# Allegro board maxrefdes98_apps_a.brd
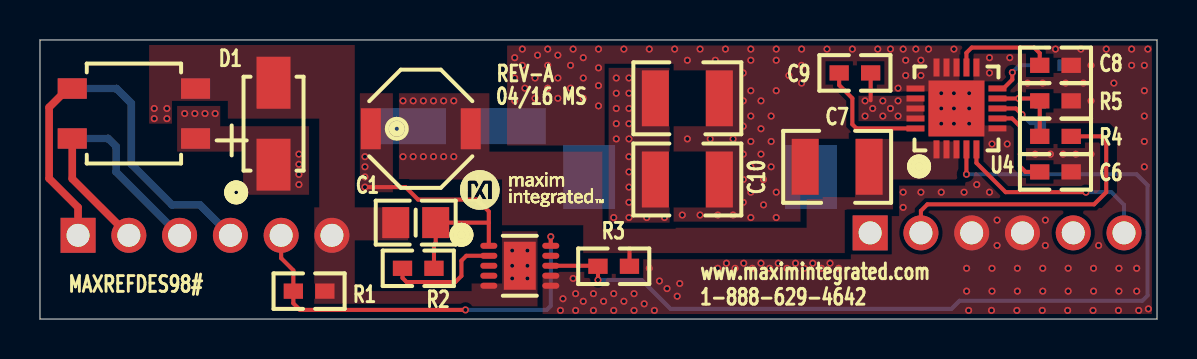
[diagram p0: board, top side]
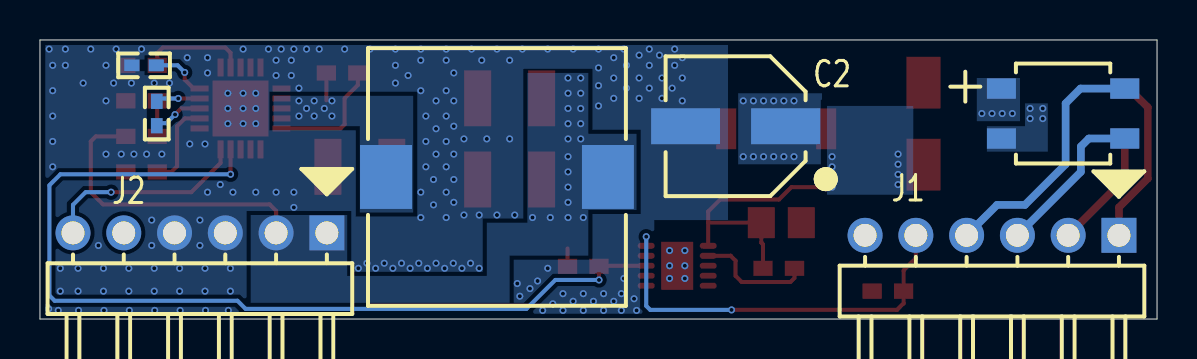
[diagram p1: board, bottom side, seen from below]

Outline 55.88 x 13.97 mm; copper layers: TOP, BOTTOM. Coordinates in mm from the lower left corner of the outline.
Outline path: 0,13.97 55.88,13.97 55.88,0 0,0 0,13.97

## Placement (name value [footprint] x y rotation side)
C1  0.1UF  [0805]  18.8 4.83 0 top
C2  22UF  [CAPAE660X770M]  21.08 9.65 0 bottom
C4  22UF  [1210]  32.39 11.05 180 top
C5  1PF  [0402]  50.04 10.29 270 bottom
C6  0.018UF  [0603]  50.8 7.37 180 top
C7  2.2UF  [1210]  39.88 7.62 0 top
C8  2.2UF  [0603]  50.8 12.7 180 top
C9  0.1UF  [0603]  40.77 12.32 0 top
C10  22UF  [1210]  32.39 6.99 180 top
D1  58V  [DIO_SMA]  11.68 9.78 90 top
EV_KIT_BOX2  MEDIUM BOX  [EVKIT_PACKAGING]  41.91 -5.21 0 top
J1  TSW-106-25-T-S-RA  [SAMTEC_TSW-106-25-X-S-RA]  1.91 4.19 0 bottom
J2  TSW-106-25-T-S-RA  [SAMTEC_TSW-106-25-X-S-RA]  41.53 4.31 0 bottom
L1  3.3UH  [IND_SD53]  19.05 9.53 0 top
L2  15UH  [IND_SLF12575]  33.02 7.11 180 bottom
NOREF  -  []  27.94 64.77 0 top
NOREF#2  -  []  21.99 6.46 0 top
NOREF#3  -  []  55.88 0 90 top
NOREF#4  -  []  0 13.97 0 top
NOREF#5  -  []  137.16 -26.04 0 top
R1  619  [0603]  13.46 1.4 180 top
R2  24.9K  [0603]  18.92 2.54 0 top
R3  3.3M  [0603]  28.7 2.64 0 top
R4  154K  [0603]  50.8 9.14 0 top
R5  34K  [0603]  50.8 10.92 180 top
R6  68K  [0402]  50.67 12.7 180 bottom
U1  KMB110F  [SOTFL125P680X160-4M]  4.7 10.29 180 top
U2  KMB110F  [SOTFL125P680X160-4M]  4.7 10.29 180 bottom
U3  MAX5969AETB+  [SON50P300X300X80-11WEED3M]  24 2.67 0 top
U4  MAX17503ATP+  [QFN50P400X400X80-21W5M]  45.85 10.54 90 top

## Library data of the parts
C1 = CAP_NP: part number: CAP_NP_0805CAP-0805,0.1UF,20-000U1-A41
C2 = CAP_POL: part number: CAP_POL_CASE_D8-CAPAE660X770M,22UF,20-0022U-59D
C4 C10 = CAP_NP: alternate symbols: CAPC3225X270L; part number: CAP_NP_1210CAP-1210,22UF,20-0022U-T7A
C5 = CAP_NP: alternate symbols: (0402_NOSILK); part number: CAP_NP_0402CAP-0402,1PF,20-0001P-32
C6 = CAP_NP: alternate symbols: (0603_NOSILK); part number: CAP_NP_0603CAP-0603,0.018UF,20-0U018-14
C7 = CAP_NP: alternate symbols: CAPC3225X270L; part number: CAP_NP_1210CAP-1210,2.2UF,20-002U2-Q1
C8 = CAP_NP: alternate symbols: 0603_NOSILK,CAPC1608X90L; part number: CAP_NP_0603CAP-0603,2.2UF,20-002U2-10
C9 = CAP_NP: alternate symbols: 0603_NOSILK,CAPC1608X90L; part number: CAP_NP_0603CAP-0603,0.1UF,20-000U1-11C
D1 = DIO_TVS: part number: DIO_TVS_UNI-DIRECT-DIO_SMA,58V,30-SMAJ58A13F-00
EV_KIT_BOX2 = EV_KIT_BOX: part number: EV_KIT_BOX_ACCESSORY-N/A,MEDIUM BOX,EVKIT_PACKAGING
J1 J2 = HEADER_6P: part number: HEADER_6P_RA-SAMTEC_TSW-106-25-X-S-RA,TSW-106-25-T-S-RA,01-TSW10625TSRA6P-19
L1 = INDUCT: part number: INDUCT_IND_SD53-IND_SD53,3.3UH,50-003U3-SM10
L2 = INDUCT: part number: INDUCT_IND_SLF12575-IND_SLF12575,15UH,50-0015U-0IU
R1 = RES: alternate symbols: (0603_NOSILK); part number: RES_0603RES-0603,619,80-0619R-24
R2 = RES: alternate symbols: 0603_NOSILK,RESC1608X90L; part number: RES_0603RES-0603,24.9K,80-024K9-24
R3 = RES: alternate symbols: (0603_NOSILK); part number: RES_0603RES-0603,3.3M,80-003M3-24
R4 = RES: alternate symbols: (0603_NOSILK); part number: RES_0603RES-0603,154K,80-0154K-24
R5 = RES: alternate symbols: (0603_NOSILK); part number: RES_0603RES-0603,34K,80-0034K-24
R6 = RES: alternate symbols: (0402_NOSILK,RESC1005X50L); part number: RES_0402RES-0402,68K,80-0068K-23
U1 U2 = DIO_SCHOTTKY_4P: part number: DIO_SCHOTTKY_4P_SMT-SOTFL125P680X160-4M,KMB110F,30-KMB110F-00
U3 = MAX5969: part number: MAX5969_TDFN10-EP-SON50P300X300X80-11WEED3M,MAX5969AETB+,10-MAX5969AETB-T
U4 = MAX17503: part number: MAX17503_TQFN20-EP-QFN50P400X400X80-21W5M,MAX17503ATP+,10-MAX17503ATP-T

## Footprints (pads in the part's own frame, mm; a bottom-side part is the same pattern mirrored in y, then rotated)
0402
  rect 0.762x0.584 smd: 1(-0.61,0) 2(0.61,0)
0603
  rect 0.965x0.762 smd: 1(-0.787,0) 2(0.787,0)
0805
  rect 1.35x1.55 smd: 1(-1,0) 2(1,0)
1210
  rect 1.35x2.8 smd: 1(-1.6,0) 2(1.6,0)
CAPAE660X770M
  rect 3.45x1.8 smd: 1(-2.5,0) 2(2.5,0)
DIO_SMA
  rect 2.6x1.7 smd: A(2.05,0) C(-2.05,0)
IND_SD53
  rect 1x2.05 smd: 1(-2.5,0) 2(2.5,0)
IND_SLF12575
  rect 2.6x3.2 smd: 1(-5.55,0) 2(5.55,0)
QFN50P400X400X80-21W5M
  rect 0.9x0.3 smd: 1(-2.05,1) 2(-2.05,0.5) 3(-2.05,0) 4(-2.05,-0.5) 5(-2.05,-1) 11(2.05,-1) 12(2.05,-0.5) 13(2.05,0) 14(2.05,0.5) 15(2.05,1)
  rect 0.3x0.9 smd: 6(-1,-2.05) 7(-0.5,-2.05) 8(0,-2.05) 9(0.5,-2.05) 10(1,-2.05) 16(1,2.05) 17(0.5,2.05) 18(0,2.05) 19(-0.5,2.05) 20(-1,2.05)
  rect 2.8x2.8 smd: 21(0,0)
SAMTEC_TSW-106-25-X-S-RA
  rect 1.75x1.75 hole 1.15: 1(0,0)
  round 1.75 hole 1.15: 2(2.54,0) 3(5.08,0) 4(7.62,0) 5(10.16,0) 6(12.7,0)
SON50P300X300X80-11WEED3M
  oval 0.85x0.3 smd: 1(-1.55,1) 2(-1.55,0.5) 3(-1.55,0) 4(-1.55,-0.5) 5(-1.55,-1) 6(1.55,-1) 7(1.55,-0.5) 8(1.55,0) 9(1.55,0.5) 10(1.55,1)
  rect 1.6x2.4 smd: 11(0,0)
SOTFL125P680X160-4M
  rect 1.45x1.02 smd: 1(-3.085,1.25) 2(-3.085,-1.25) 3(3.085,-1.25) 4(3.085,1.25)

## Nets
ADJ: C5.1 R4.1 R5.2 U4.9(FB)
CP1: J1.5 R1.2 U3.10(CLS)
CP2: C1.1 D1.A J1.6 R1.1 U1.2(-) U2.2(-) U3.5(VSS) U3.11(EP)
PG: R3.1 U3.8(PG) U4.4(EN/UVLO)
RST: J2.6 U4.5(RESET)
SUPPLY_0: C2.2(B) C4.1 C6.1 C7.1 C8.1 C10.1 J2.3 J2.4 R5.1 R6.1 U3.6(RTN) U3.7(WAD) U4.6(SYNC) U4.11(MODE) U4.13(SGND) U4.14(PGND1) U4.15(PGND2) U4.16(PGND3) U4.21(EP)
UNNAMED_1_CAPNP_I5_2: C1.2 D1.C(K) L1.1 R2.2 U1.1(+) U2.1(+) U3.1(VDD)
UNNAMED_1_CAPNP_I12_2: C6.2 U4.7(SS)
UNNAMED_1_CAPNP_I16_2: C2.1(A) C7.2 L1.2 R3.2 U4.1(VIN1) U4.2(VIN2) U4.3(VIN3)
UNNAMED_1_CAPNP_I17_2: C8.2 U4.12(VCC)
UNNAMED_1_CAPNP_I19_2: C4.2 C10.2 J2.1 J2.2 L2.2 R4.2
UNNAMED_1_CAPNP_I23_1: C9.1 U4.20(BST)
UNNAMED_1_CAPNP_I23_2: C9.2 L2.1 U4.17(LX1) U4.18(LX2) U4.19(LX3)
UNNAMED_1_CAPNP_I26_2: C5.2 U4.8(CF)
UNNAMED_1_MAX5969_I24_DET: R2.1 U3.2(DET)
UNNAMED_1_MAX17503_I11_RT: R6.2 U4.10(RT)
VA1: J1.1 U1.3(AC1)
VA2: J1.2 U1.4(AC2)
VB1: J1.3 U2.3(AC1)
VB2: J1.4 U2.4(AC2)

Pads without a net: J2 5; U3 3 4 9

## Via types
v1: diameter 0.356, hole 0.203, TOP to BOTTOM, 261 vias

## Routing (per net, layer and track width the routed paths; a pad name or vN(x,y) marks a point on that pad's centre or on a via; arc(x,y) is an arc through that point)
ADJ: length 5.1
  TOP w0.203: R4.1 R5.2 49.89,11.04 v1(48.96,11.04) U4.9
  BOTTOM w0.203: v1(48.96,11.04) 49.89,11.04 C5.1
CP1: length 20.7
  TOP w0.203: v1(21.29,0.46) 13,0.46 12.67,0.79 R1.2 12.67,2.44 12.07,3.05 J1.5 ; U3.10 v1(25.55,4.12)
  BOTTOM w0.203: v1(21.29,0.46) 25.35,0.46 25.55,0.66 v1(25.55,4.12)
CP2: length 0.3
  TOP w0.203: 22.18,1.67 U3.5
  vias: v1(5.71,10.54) v1(5.71,10.03) v1(6.35,10.54) v1(6.35,10.03) v1(23.62,3.43) v1(23.62,2.67) v1(23.62,2.03) v1(24.38,3.43) v1(24.38,2.67) v1(24.38,2.03)
PG: length 47.5
  TOP w0.203: U3.8 27.89,2.67 R3.1 v1(27.91,1.96) ; U4.4 v1(46.35,7.25)
  BOTTOM w0.203: v1(46.35,7.25) 54.86,7.25 55.41,6.69 55.41,1.18 55.14,0.91 46,0.91 45.59,0.51 31.55,0.51 30.1,1.96 v1(27.91,1.96)
RST: length 10.3
  TOP w0.203: v1(52.32,6.35) 48.31,6.35 46.85,7.81 U4.5
  BOTTOM w0.203: J2.6 54.23,5.71 53.59,6.35 v1(52.32,6.35)
SUPPLY_0:
  vias: v1(23.75,13.08) v1(23.75,12.07) v1(23.75,10.92) v1(24.13,13.51) v1(24.13,12.7) v1(24.26,11.56) v1(24.77,12.07) v1(24.77,11.05) v1(24.89,13.21) v1(25.4,13.51) v1(25.4,12.7) v1(25.4,11.56) v1(25.91,13.21) v1(25.91,12.07) v1(25.91,11.05) v1(26.04,0.43) v1(26.16,1.02) v1(26.54,12.7) v1(26.54,11.56) v1(26.67,13.51) v1(26.67,2.03) v1(26.8,1.27) v1(26.8,0.43) v1(27.18,13.08) v1(27.18,12.07) v1(27.18,11.05) v1(27.18,0.89) v1(27.69,1.27) v1(27.69,0.43) v1(27.94,13.51) v1(27.94,12.57) v1(27.94,11.68) v1(27.94,10.67) v1(28.19,0.89) v1(28.7,1.27) v1(28.7,0.43) v1(29.21,13.51) v1(29.21,0.89) v1(29.72,1.27) v1(29.72,0.43) v1(30.23,0.76) v1(30.48,13.51) v1(30.48,2.54) v1(30.73,0.43) v1(30.99,1.91) v1(31.37,1.52) v1(31.75,13.51) v1(31.88,1.14) v1(32,1.78) v1(32.13,5.21) v1(32.39,12.95) v1(32.39,9.02) v1(33.02,13.51) v1(33.02,5.21) v1(33.53,9.02) v1(33.78,12.95) v1(33.91,5.21) v1(33.91,2.54) v1(34.29,13.51) v1(34.34,2.79) v1(34.67,9.02) v1(34.67,5.21) v1(34.77,2.54) v1(35.18,12.32) v1(35.18,10.92) v1(35.18,9.65) v1(35.18,8.26) v1(35.18,6.99) v1(35.18,5.84) v1(35.2,2.79) v1(35.56,13.51) v1(35.56,12.95) v1(35.56,11.43) v1(35.56,10.16) v1(35.56,8.89) v1(35.56,7.62) v1(35.56,6.35) v1(35.56,5.08) v1(35.64,2.54) v1(36.07,10.92) v1(36.07,9.53) v1(36.07,8.26) v1(36.07,2.79) v1(36.2,6.99) v1(36.2,5.71) v1(36.58,10.16) v1(36.58,8.89) v1(36.58,7.62) v1(36.5,2.54) v1(36.83,13.51) v1(36.83,12.95) v1(36.83,11.43) v1(36.83,6.35) v1(36.83,5.08) v1(36.93,2.79) v1(37.36,2.54) v1(37.47,12.19) v1(37.8,2.79) v1(38.1,13.51) v1(38.1,12.7) v1(38.1,11.81) v1(38.23,2.54) v1(38.66,2.79) v1(39.09,2.54) v1(39.37,13.51) v1(39.52,2.79) v1(39.95,2.54) v1(40.64,13.51) v1(41.91,13.51) v1(42.55,13.51) v1(42.93,11.56) v1(43.18,13.51) v1(43.18,6.35) v1(43.18,5.59) v1(43.31,12.95) v1(43.31,12.19) v1(43.81,13.51) v1(44.07,12.95) v1(44.07,12.19) v1(44.07,6.35) v1(44.45,13.51) v1(45.09,11.3) v1(45.09,10.54) v1(45.09,9.78) v1(45.09,6.35) v1(45.72,13.51) v1(45.72,11.3) v1(45.72,10.54) v1(45.72,9.78) v1(46.23,6.35) v1(46.36,2.54) v1(46.36,1.4) v1(46.48,11.3) v1(46.48,10.54) v1(46.48,9.78) v1(46.46,0.43) v1(46.86,6.73) v1(47.5,13.08) v1(47.5,12.32) v1(47.5,6.35) v1(47.62,8.76) v1(47.62,2.54) v1(47.62,1.4) v1(47.6,0.43) v1(47.88,4.95) v1(47.88,3.68) v1(48.39,8.76) v1(48.51,13.08) v1(48.87,0.43) v1(48.89,2.54) v1(48.89,1.4) v1(49.4,11.81) v1(49.78,8.26) v1(50.17,11.81) v1(50.17,2.54) v1(50.17,1.4) v1(50.14,0.43) v1(50.29,4.95) v1(50.29,3.68) v1(50.55,8.26) v1(50.8,13.51) v1(51.18,8.26) v1(51.31,11.81) v1(51.44,2.54) v1(51.44,1.4) v1(51.41,0.43) v1(51.82,8.26) v1(52.07,13.51) v1(52.2,11.81) v1(52.58,12.7) v1(52.58,10.92) v1(52.58,8.26) v1(52.68,0.43) v1(52.7,2.54) v1(52.7,1.4) v1(52.96,3.68) v1(53.34,13.51) v1(53.72,11.81) v1(53.98,2.54) v1(53.98,1.4) v1(53.95,0.43) v1(54.61,13.51) v1(54.61,12.7) v1(54.86,2.54) v1(54.86,1.4) v1(54.97,0.43) v1(55.25,12.7) v1(55.25,11.43) v1(55.25,10.16) v1(55.25,8.89) v1(55.25,7.62) v1(55.42,13.51) v1(55.45,0.51)
UNNAMED_1_CAPNP_I5_2: length 13.4
  TOP w0.203: v1(16.26,6.6) 18.29,6.6 18.91,5.98 21.86,5.98 22.45,5.39 22.45,4.83 ; 22.45,4.83 C1.2 19.8,3.82 19.71,3.74 R2.2 ; 22.45,4.83 U3.1
  vias: v1(7.24,10.29) v1(7.75,10.29) v1(8.26,10.29) v1(8.76,10.29) v1(12.95,8.26) v1(12.95,7.75) v1(12.95,7.24) v1(12.95,6.73) v1(16.26,8.13) v1(16.26,7.62) v1(16.26,7.11)
UNNAMED_1_CAPNP_I12_2: length 4.4
  TOP w0.203: U4.7 48.63,10.04 49.02,9.65 49.02,7.65 49.3,7.37 50.01,7.37
UNNAMED_1_CAPNP_I16_2: length 0.9
  TOP w0.203: R3.2 29.49,3.53
  vias: v1(18.16,10.92) v1(18.16,8.13) v1(18.67,10.92) v1(18.67,8.13) v1(19.18,10.92) v1(19.18,8.13) v1(19.69,10.92) v1(19.69,8.13) v1(20.19,10.92) v1(20.19,8.13) v1(20.7,10.92) v1(20.7,8.13)
UNNAMED_1_CAPNP_I17_2: length 5.2
  TOP w0.203: U4.12 46.35,13.33 46.61,13.59 49.73,13.59 50.01,13.31 C8.2
UNNAMED_1_CAPNP_I19_2: length 15.2
  TOP w0.203: R4.2 53.09,9.14 53.34,8.89 53.34,6.35 52.73,5.74 44.39,5.74 44.07,5.42 J2.2
  vias: v1(28.7,5.08) v1(28.83,12.07) v1(28.83,11.3) v1(28.83,10.54) v1(28.83,9.78) v1(28.83,9.02) v1(29.46,12.07) v1(29.46,11.3) v1(29.46,10.54) v1(29.46,9.78) v1(29.46,9.02) v1(29.46,8.13) v1(29.46,7.37) v1(29.46,6.6) v1(29.46,5.84) v1(29.46,5.08) v1(30.35,5.08) v1(31.24,5.08)
UNNAMED_1_CAPNP_I23_1: length 6.1
  TOP w0.203: C9.1 39.98,11.71 40.64,11.05 40.64,9.74 40.84,9.54 U4.20
UNNAMED_1_CAPNP_I23_2: length 1.4
  TOP w0.203: 41.55,10.95 C9.2
  vias: v1(41.28,10.92) v1(41.28,10.16) v1(41.66,10.54) v1(42.16,10.92) v1(42.16,10.16) v1(42.55,10.54) v1(42.93,10.92) v1(42.93,10.16)
UNNAMED_1_CAPNP_I26_2: length 2.5
  TOP w0.203: v1(49.12,10.24) 48.82,10.54 U4.8
  BOTTOM w0.203: v1(49.12,10.24) 49.56,9.8 49.91,9.8 C5.2
UNNAMED_1_MAX5969_I24_DET: length 5.9
  TOP w0.203: U3.2 21.33,3.17 21.08,2.92 21.08,2.16 20.78,1.85 18.34,1.85 18.14,2.06 R2.1
UNNAMED_1_MAX17503_I11_RT: length 2.9
  TOP w0.203: v1(48.64,12.34) 48.64,11.98 48.2,11.54 U4.10
  BOTTOM w0.203: R6.2 49,12.7 v1(48.64,12.34)
VA1: length 8.6
  TOP w0.381: U1.3 1.4,11.54 0.46,10.6 0.46,7.04 1.91,5.59 J1.1
VA2: length 6
  TOP w0.381: U1.4 1.61,7.02 J1.2
VB1: length 8.1
  BOTTOM w0.381: J1.3 3.81,7.37 3.81,8.64 3.41,9.04 U2.3
VB2: length 12.7
  BOTTOM w0.381: U2.4 3.83,11.54 4.57,10.79 4.57,7.75 6.6,5.71 8,5.71 J1.4

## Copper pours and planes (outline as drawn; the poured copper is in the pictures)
CP2 on TOP: 6.6,9.78 6.6,10.92 9.4,10.92 9.4,10.03 13.97,10.03 13.97,5.59 13.72,5.59 13.72,0.64 24.89,0.64 24.89,4.45 23.11,4.45 23.11,1.78 21.59,1.78 21.59,1.4 15.75,1.4 15.75,3.94 18.41,3.94 18.41,5.59 15.75,5.59 15.75,13.72 5.46,13.72 5.46,9.78
CP2 on BOTTOM: 8.51,9.65 6.6,9.65 6.6,10.79 5.46,10.79 5.46,8.38 8.51,8.38
SUPPLY_0 on TOP: 25.15,0.25 25.15,4.95 23.37,4.95 23.37,13.69 55.63,13.69 55.63,0.25 ; 4 cut-outs
SUPPLY_0 on BOTTOM: 25.15,0.27 25.15,4.95 21.46,4.95 21.46,13.72 55.61,13.72 55.61,0.27
UNNAMED_1_CAPNP_I5_2 on TOP: 16,11.3 16,6.35 17.65,6.35 17.65,11.3
UNNAMED_1_CAPNP_I5_2 on TOP: 6.86,10.67 6.86,8.38 10.16,8.38 10.16,6.22 13.46,6.22 13.46,9.65 9.02,9.65 9.02,10.67
UNNAMED_1_CAPNP_I5_2 on BOTTOM: 6.86,12.07 6.86,9.91 9.02,9.91 9.02,12.07
UNNAMED_1_CAPNP_I5_2 on BOTTOM: 12.19,10.67 16.51,10.67 16.51,6.22 12.19,6.22
UNNAMED_1_CAPNP_I16_2 on TOP: 40.77,9.02 42.67,9.02 42.67,8.89 45.97,8.89 45.97,6.99 42.67,6.99 42.67,5.46 40.26,5.46 40.26,3.3 27.18,3.3 27.18,4.7 23.11,4.7 23.11,6.99 17.96,6.99 17.96,11.3 22.48,11.3 22.48,8.38 28.19,8.38 28.19,4.57 38.35,4.57 38.35,6.1 40.77,6.1
UNNAMED_1_CAPNP_I16_2 on BOTTOM: 20.96,7.75 16.76,7.75 16.76,11.3 20.96,11.3
UNNAMED_1_CAPNP_I19_2 on TOP: 28.45,12.57 31.5,12.57 31.5,4.83 28.45,4.83
UNNAMED_1_CAPNP_I19_2 on BOTTOM: 28.45,12.32 31.5,12.32 31.5,4.83 33.53,4.83 33.53,2.16 40.51,2.16 40.51,5.21 45.34,5.21 45.34,0.76 32.39,0.76 32.39,3.18 28.45,3.18 28.45,5.46 26.04,5.46 26.04,9.27 28.45,9.27
UNNAMED_1_CAPNP_I23_2 on TOP: 44.2,11.18 40.89,11.18 40.89,9.91 44.2,9.91
UNNAMED_1_CAPNP_I23_2 on BOTTOM: 44.2,11.18 37.21,11.18 37.21,5.33 39.88,5.33 39.88,9.65 44.2,9.65

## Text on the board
Ref Des/Silkscreen Top: MAXREFDES98# | 04/16 MS | REV-A | 1-888-629-4642 | www.maximintegrated.com
DISPLAY_TOP: FIGURE | SIZE | 8.0 | 45.28 | TOLERANCE | +3.0/-6.0 | +3.0/-3.0 | PLATED | ALL UNITS ARE IN MILS | QTY | 261 | 12 | NOTES | DRILL CHART: TOP to BOTTOM
User.12: NOTES: | FINISH: | TESTING: | MISCELLANEOUS: | TOOLING: | 16.  VENDOR LOGO & DATE CODE REQUIRED IN INK ON BOTTOM SIDE ONLY. DATE CODE FORMAT MUST BE YYWW ONLY | 17.  FINAL ELECTRICAL TEST TO BE PERFORMED USING PROVIDED IPC-D-356A NETLIST OR ODB++ FORMAT FILE. | 18.  A TIME DOMAIN REFLECTOMETER REPORT FOR EACH IMPEDANCE CONTROLLED LAYER AND A CERTIFICATE | 15.  CHECK ALL THAT APPLY | 14.  CHECK ALL THAT APPLY | 19. IF PRESENT, ALL BLIND/BURIED VIAS WITH AN ASPECT RATIO <1:1 TO BE PLATED SHUT WITH COPPER WHEN | 20.  FOR ALL DRILL INFORMATION REFER TO DRILL CHART. | 21.  FINISHED SURFACE CONTACTS AND FILLED VIAS TO BE FREE OF ANY PITS. SCRATCHES PROBE MARKS | 23.  PEMNUT | 13.  DRILL SIZES ARE FINISHED HOLE SIZES. ALL HOLES SHALL BE LOCATED WITHIN .005 DTP. | 22.  THIEVING: | 9.  ALL TRACES FILLETED OPTION TO ENHANCE RELIABILITY AT PAD JUNCTIONS | 10.  LAYER TO LAYER REGISTRATIONS SHALL BE WITHIN .003 INCHES. | MATERIAL: | 11.  PLATING SPECIFICATION: | 12.  CHECK ALL THAT APPLY | 8.  IF STATED IN THE LAMINATION DIAGRAM, THE DIELECTRIC THICKNESS OF ANY | 1.  DIMENSIONS ARE IN INCHES (EXCEPT WHERE NOTED). | 3.  THE PCB SHALL BE FABRICATED TO IPC-6012, TYPE X, CLASS 2. | 4.  BOARD MATERIAL & CONSTRUCTION SHALL MEET THE REQUIREMENTS OF UL796 | 5.  OVERALL BOARD THICKNESS REFER TO LAMINATION DIAGRAM. TOLERANCE APPLIES | 6.  BOW & TWIST NOT TO EXCEED 0.0075 IN. (0.75%) PER LINEAR INCH. | 7.  PHOTO ETCH CIRCUITRY PER ENCLOSED GERBER RS274X OR ODB++ FORMAT FILE. | 2.  BOARD MATERIAL: | ( )  FINISH CONDUCTOR SURFACES: IMMERSION GOLD, 2-5 MICRO INCHES OVER | (X)  STARTING COPPER WEIGHT FOR OUTER LAYERS TO BE (1 OZ), THE FINISH COPPER WEIGHT IS (1 OZ). | ( )  STARTING COPPER WEIGHT FOR OUTER LAYERS TO BE (1 OZ), THE FINISH COPPER WEIGHT IS (2 OZ). | ( )  STARTING COPPER WEIGHT FOR OUTER LAYERS TO BE (2 OZ), THE FINISH COPPER WEIGHT IS (2 OZ)MINIMUM. | ( )  OTHER ________________________ | (X)  FINISH CONDUCTOR SURFACES: IMMERSION GOLD, 3-8 MICRO INCHES OVER | ( )  FINGERS TO BE GOLD PLATED. | ( )  LEAD FREE AND RoHS COMPLIANT PLATING. | (X)  GREEN SOLDERMASK OVER BARE COPPER/BARE GOLD (BOTH SIDES) WITH LIQUID PHOTO IMAGEABLE INK (LPI) | ( )  GREEN TAIYO PSR-4000 | ( )  ELECTRODEPOSITED HARD GOLD PLATE, TYPE 1 (99.7% MIN GOLD), GRADE C | (X)  APPLY SILKSCREEN USING A NON-CONDUCTIVE, WHITE EPOXY | THE STARTING WEIGHT CAN BE (0.5 OZ) AS LONG AS THE FINISH COPPER WEIGHT IS (2 OZ). | THE STARTING WEIGHT CAN BE (<2 OZ) AS LONG AS THE FINISH COPPER WEIGHT IS (2 OZ). | MINIMUM BARREL PLATING OF .001 IN. PLATED HOLES SHALL NOT BE ROUGH OR IRREGULAR | SO AS TO HINDER PROPER SOLDER WICKING. | USED AS VIA-IN PAD OR AS A STACKED VIA. BLIND/BURIED VIAS WITH AN ASPECT RATIO >1:1 TO BE FILLED | WITH NON-CONDUCTIVE EPOXY. UNLESS OTHERWISE SPECIFIED. | ( )  NON-CONDUCTIVE EPOXY. FILL AND CAP ALL 0.XXXX INCH DRILLED VIAS. | ( )  SILVER. FILL AND CAP ALL 0.XXXX INCH DRILLED VIAS. | (REQUIRED UNLESS OTHERWISE SPECIFIED IN QUOTE) | THE PCB SHALL HAVE A VERIFICATION STAMP. | OF COMPLIANCE SHALL BE PROVIDED BY VENDOR AT TIME OF SHIPMENT. | OR OTHER DEFORMITIES THAT COULD EFFECT THE APPERANCE AND PERFORMACE OF THE CONTACT | SURFACE. CONTACTS ARE TO BE AS FLAT AS POSSIBLE. NOT TO EXCEED +/- 0.001" OF FLATNESS. | ( )  SUPPLIER MAY ADD THIEVING TO COMPENSATE FOR LOW COPPER DENSITY AREAS ON THIS DESIGN. | WHERE SPACING PERMITS. | LEGEND TO LEGEND +/- 0.007 INCHES | (X)  SUPPLIER MAY NOT ADD THIEVING TO COMPENSATE FOR LOW COPPER DENSITY AREAS ON THIS DESIGN. | ( )  PEMNUTS TO BE INSTALLED BY SUPPLIER. | ( )  PEMNUTS NOT TO BE INSTALLED BY SUPPLIER. | (X)  NOT APPLICABLE | CONTROLLED IMPEDANCE LAYER IS FOR REFERENCE ONLY. FINAL ACCEPTANCE | SHALL BE DETERMINED BY THESE LAYERS HAVING A CHARACTERISTIC | IMPEDANCE OF +/-10% OHMS AS STATED IN THE LAMINATION DIAGRAM. THE | VENDOR CAN MAKE ADJUSTMENTS AS LONG AS THE STATED IMPEDANCE AND | OVERALL BOARD THICKNESS IS MAINTAINED. ANY ADJUSTMENT MADE TO TRACE | WIDTH OR SPACING MUST HAVE PRIOR WRITTEN APPROVAL FROM MAXIM. | ( )  FILLETED | (X)  NOT FILLETED | (X)  ISOLA 370HR OR EQUIVALENT | ( )  NELCO-4000-13 | ( )  MEGTRON 6 | ( )  ROGERS 4350B | ( )  ROGERS 4003C | ( )  ISOLA-FR408HR OR EQUIVALENT | WORKMANSHIP SHALL CONFORM TO IPC-A-600, CLASS 2, CURRENT REVISIONS. | WITH FLAMMABILITY RATING OF 94V-O. | AFTER ALL LAMINATION AND PLATING PROCESSES. IT IS TO BE MEASURED FROM | TOP PCB METAL TO BOTTOM PCB METAL UNLESS OTHERWISE SPECIFIED. | BOW & TWIST SHOULD BE MEASURED PER IPC-TM-650, METHOD 2.4.22. | DRILL LOCATION AND SIZE CONTROLLED BY EXCELLON CNC DRILL FILE. | FOR OUTER LAYERS WHERE SPACING PREVENTS THE USE OF (1 OZ) AS A STARTING WEIGHT, | FOR OUTER LAYERS WHERE SPACING PREVENTS THE USE OF (2 OZ) AS A STARTING WEIGHT, | UNLESS OTHERWISE SPECIFIED | FOR OUTER LAYERS WHERE SPACING PREVENTS THE USE OF (1 OZ) AS A STARTING WEIGHT | THE STARTING WEIGHT CAN BE (0.5 OZ) AS LONG AS THE FINISH COPPER WEIGHT IS (1 OZ) | (KNOOP HARDNESS 130-200), CLASS 1 (50-100 MICRO INCHES THICK) IN ACCORDANCE WITH MIL-G-45204C. | GENERAL SURFACING REQUIREMENTS MUST MEET ANSI/IPC-A-600(CURRENT REV) SECTION 4.0, | CLASS 3 (50-100 MICROINCHES THICK) OVER ELECTRODEPOSITED NICKEL PLATE | IN ACCORDANCE WITH ANSI/IPC-A-600D, SECTION 4.0, CLASS 3 (200-600 MICROINCHES THICK). | 100 MICRO INCHES MINIMUM OF ELECTROLESS NICKEL. | 118-236 MICRO INCHES MINIMUM OF ELECTROLESS NICKEL. | PER ARTWORK. | BASED INK PER ARTWORK. | (USE CHECKED ITEMS FOR MATERIAL) | (USE CHECKED ITEMS FOR PLATING) | (USE CHECKED ITEMS FOR TOOLING) | UNLESS OTHERWISE SPECIFIED: | FRANK PAN | 04/26/16 | P2 | A | P1 | REVISION RELEASE | PRODUCTION RELEASE | INITIAL RELEASE | FP | 03/02/16 | 12/08/15
